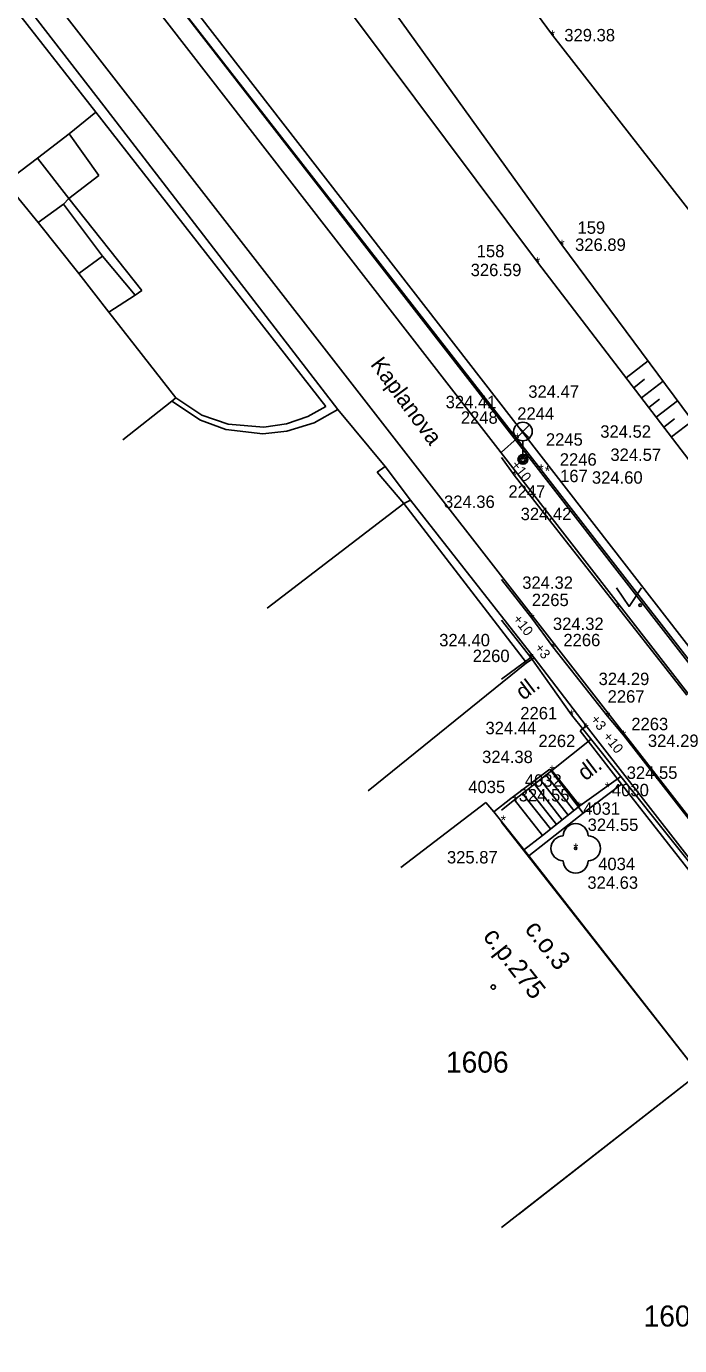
# Model space of a CAD drawing. Extents: x -600587 to -600377, y -1159886 to -1159708.
# Drawn here: x -600539.9 to -600513.6, y -1159856.5 to -1159803.3 of the extents above; entities that cross this region are included whole.
import ezdxf

# ---------------------------------------------------------------- set-up
doc = ezdxf.new("R2010")
doc.units = 0
for name, color, linetype in [('Hranice parcel', 7, 'Continuous'), ('Level 33', 7, 'Continuous'), ('Parcelní čísla', 7, 'Continuous'), ('Vnitřní kresba', 7, 'Continuous'), ('Vrstva 10', 7, 'Continuous'), ('Vrstva 11', 7, 'Continuous'), ('Vrstva 16', 7, 'Continuous'), ('Vrstva 20', 7, 'Continuous'), ('Vrstva 22', 7, 'Continuous'), ('Vrstva 36', 7, 'Continuous'), ('Vrstva 40', 7, 'Continuous'), ('Vrstva 46', 7, 'Continuous'), ('Vrstva 58', 7, 'Continuous'), ('Vrstva 59', 7, 'Continuous'), ('Vrstva 60', 7, 'Continuous'), ('Vrstva 7', 7, 'Continuous'), ('Značky budov', 7, 'Continuous')]:
    doc.layers.add(name, color=color, linetype=linetype)

msp = doc.modelspace()

# ---------------------------------------------------------------- linework, layer by layer
at = {"layer": 'Hranice parcel'}
msp.add_line((-600519.44, -1159828.81), (-600524.43, -1159822.45), dxfattribs=at)
for points in [[(-600488.61, -1159847.98), (-600490.62, -1159848.62), (-600491.99, -1159848.82), (-600493.39, -1159848.77), (-600494.93, -1159848.62), (-600496.36, -1159848.13), (-600500.23, -1159845.75), (-600572.32, -1159752.89), (-600572.98, -1159751.48), (-600573.33, -1159750.24), (-600573.44, -1159748.95), (-600573.44, -1159747.6), (-600573.32, -1159746.25), (-600573.13, -1159744.93), (-600572.66, -1159743.72), (-600571.05, -1159741.4), (-600570.22, -1159740.33), (-600564.67, -1159736.09)], [(-600524.43, -1159822.45), (-600525.46, -1159821.09), (-600527.36, -1159818.8), (-600536.8, -1159806.55), (-600551.99, -1159786.94)], [(-600530.213, -1159826.814), (-600524.7, -1159822.59), (-600524.43, -1159822.45)], [(-600519.44, -1159828.81), (-600519.76, -1159829.02), (-600526.14, -1159834.179)], [(-600508.85, -1159842.47), (-600517.35, -1159831.56), (-600519.44, -1159828.81)], [(-600520.064, -1159851.241), (-600512.8, -1159845.57), (-600512.33, -1159845.23), (-600509.08, -1159842.66), (-600508.85, -1159842.47)]]:
    msp.add_lwpolyline(points, dxfattribs=at)
at = {"layer": 'Level 33'}
for p, q in [((-600520.163, -1159819.947), (-600519.633, -1159819.417)), ((-600520.163, -1159819.417), (-600519.633, -1159819.947)), ((-600519.898, -1159820.057), (-600519.898, -1159820.807))]:
    msp.add_line(p, q, dxfattribs=at)
for centre, radius in [((-600519.898, -1159819.682), 0.375), ((-600519.898, -1159820.807), 0.2), ((-600519.898, -1159820.807), 0.145), ((-600519.898, -1159820.807), 0.0876)]:
    msp.add_circle(centre, radius, dxfattribs=at)
at = {"layer": 'Vnitřní kresba'}
for p, q in [((-600580.267, -1159748.971), (-600497.15, -1159855.9)), ((-600499.96, -1159845.44), (-600571.89, -1159752.7)), ((-600503.93, -1159842.26), (-600567.61, -1159760.2)), ((-600537.12, -1159806.8), (-600552.47, -1159787.22)), ((-600538.2, -1159807.68), (-600537.12, -1159806.8)), ((-600527.85, -1159818.67), (-600537.12, -1159806.8)), ((-600539.47, -1159808.66), (-600538.2, -1159807.68)), ((-600538.2, -1159807.68), (-600537, -1159809.36)), ((-600540.77, -1159809.64), (-600539.47, -1159808.66)), ((-600539.47, -1159808.66), (-600538.21, -1159810.29)), ((-600537, -1159809.36), (-600538.21, -1159810.29)), ((-600540.77, -1159809.64), (-600539.44, -1159811.25)), ((-600538.43, -1159810.52), (-600539.44, -1159811.25)), ((-600538.21, -1159810.29), (-600538.43, -1159810.52)), ((-600538.43, -1159810.52), (-600536.85, -1159812.62)), ((-600538.21, -1159810.29), (-600535.26, -1159814)), ((-600539.44, -1159811.25), (-600537.81, -1159813.31)), ((-600537.81, -1159813.31), (-600536.85, -1159812.62)), ((-600536.85, -1159812.62), (-600535.54, -1159814.19)), ((-600537.81, -1159813.31), (-600536.59, -1159814.87)), ((-600535.54, -1159814.19), (-600536.59, -1159814.87)), ((-600535.26, -1159814), (-600535.54, -1159814.19)), ((-600536.59, -1159814.87), (-600533.9, -1159818.33)), ((-600534.06, -1159818.46), (-600536.028, -1159820.024)), ((-600533.9, -1159818.33), (-600534.06, -1159818.46)), ((-600534.06, -1159818.46), (-600532.9, -1159819.23)), ((-600533.9, -1159818.33), (-600532.85, -1159819.03)), ((-600531.79, -1159819.39), (-600532.85, -1159819.03)), ((-600529.43, -1159819.37), (-600528.57, -1159819.08)), ((-600527.85, -1159818.67), (-600528.57, -1159819.08)), ((-600527.36, -1159818.8), (-600528.31, -1159819.34)), ((-600531.88, -1159819.6), (-600532.9, -1159819.23)), ((-600531.88, -1159819.6), (-600530.39, -1159819.78)), ((-600531.79, -1159819.39), (-600530.35, -1159819.51)), ((-600529.43, -1159819.37), (-600530.35, -1159819.51)), ((-600529.42, -1159819.67), (-600528.31, -1159819.34)), ((-600529.42, -1159819.67), (-600530.39, -1159819.78)), ((-600525.46, -1159821.09), (-600525.77, -1159821.33)), ((-600525.77, -1159821.33), (-600524.7, -1159822.59)), ((-600524.7, -1159822.59), (-600519.76, -1159829.02)), ((-600517.35, -1159831.56), (-600517.59, -1159831.76)), ((-600517.59, -1159831.76), (-600515.92, -1159833.9)), ((-600520.38, -1159834.48), (-600518.81, -1159833.3)), ((-600518.81, -1159833.3), (-600517.47, -1159835.08)), ((-600517.47, -1159835.08), (-600515.92, -1159833.9)), ((-600515.92, -1159833.9), (-600509.08, -1159842.66)), ((-600521.07, -1159835.02), (-600520.38, -1159834.48)), ((-600524.823, -1159837.271), (-600521.39, -1159834.65)), ((-600521.39, -1159834.65), (-600521.07, -1159835.02)), ((-600521.07, -1159835.02), (-600519.66, -1159836.79)), ((-600518.98, -1159836.26), (-600517.47, -1159835.08)), ((-600519.66, -1159836.79), (-600518.98, -1159836.26)), ((-600519.66, -1159836.79), (-600512.8, -1159845.57))]:
    msp.add_line(p, q, dxfattribs=at)
at = {"layer": 'Vrstva 10'}
for p, q in [((-600519.583, -1159828.799), (-600517.941, -1159831.105)), ((-600517.941, -1159831.105), (-600517.443, -1159831.729))]:
    msp.add_line(p, q, dxfattribs=at)
at = {"layer": 'Vrstva 11'}
for p, q in [((-600515.73, -1159817.52), (-600514.85, -1159816.84)), ((-600515.43, -1159817.92), (-600514.99, -1159817.58)), ((-600515.12, -1159818.32), (-600514.25, -1159817.65)), ((-600514.82, -1159818.71), (-600514.39, -1159818.38)), ((-600514.52, -1159819.11), (-600513.66, -1159818.45)), ((-600514.21, -1159819.51), (-600513.78, -1159819.18)), ((-600513.91, -1159819.9), (-600513.06, -1159819.25)), ((-600520.767, -1159820.512), (-600520.128, -1159819.959)), ((-600520.767, -1159820.735), (-600520.248, -1159821.439)), ((-600520.248, -1159821.439), (-600513.287, -1159830.311)), ((-600520.767, -1159825.65), (-600519.539, -1159827.217)), ((-600519.539, -1159827.217), (-600518.688, -1159828.374)), ((-600518.688, -1159828.374), (-600516.483, -1159831.169)), ((-600519.583, -1159828.799), (-600520.767, -1159829.678)), ((-600516.483, -1159831.169), (-600515.844, -1159831.929)), ((-600517.153, -1159832.092), (-600518.731, -1159833.352)), ((-600515.844, -1159831.929), (-600508.09, -1159841.905)), ((-600520.239, -1159834.538), (-600518.731, -1159833.352)), ((-600518.731, -1159833.352), (-600517.604, -1159834.785)), ((-600519.438, -1159833.908), (-600518.311, -1159835.341)), ((-600519.203, -1159833.723), (-600518.076, -1159835.156)), ((-600518.967, -1159833.537), (-600517.84, -1159834.97)), ((-600515.957, -1159833.591), (-600517.604, -1159834.785)), ((-600519.91, -1159834.279), (-600518.783, -1159835.712)), ((-600519.674, -1159834.094), (-600518.547, -1159835.527)), ((-600520.767, -1159834.954), (-600520.239, -1159834.538)), ((-600520.239, -1159834.538), (-600519.112, -1159835.971)), ((-600517.604, -1159834.785), (-600519.112, -1159835.971)), ((-600519.877, -1159836.573), (-600519.112, -1159835.971))]:
    msp.add_line(p, q, dxfattribs=at)
for points in [[(-600502.72, -1159834.41), (-600509.56, -1159825.58), (-600519.31, -1159812.85), (-600530.48, -1159797.91), (-600554.16, -1159766.46)], [(-600541.29, -1159772.5), (-600530.96, -1159787.09), (-600518.71, -1159803.7), (-600511.21, -1159813.31), (-600502.87, -1159824.07)], [(-600508.65, -1159825.2), (-600518.33, -1159812.15), (-600529.24, -1159796.96), (-600545.67, -1159772.91)]]:
    msp.add_lwpolyline(points, dxfattribs=at)
at = {"layer": 'Vrstva 20'}
for points in [[(-600512.8, -1159845.57), (-600520.767, -1159835.442)], [(-600502.538, -1159860.037), (-600504.48, -1159857.53), (-600503.89, -1159857.08), (-600512.8, -1159845.57), (-600520.767, -1159851.79)]]:
    msp.add_lwpolyline(points, dxfattribs=at)
at = {"layer": 'Vrstva 22'}
msp.add_circle((-600517.771, -1159836.495), 0.05, dxfattribs=at)
for centre, start, end in [((-600517.771, -1159835.995), 0, 180), ((-600518.271, -1159836.495), 90, 270), ((-600517.271, -1159836.495), 270, 90), ((-600517.771, -1159836.995), 180, 0)]:
    msp.add_arc(centre, 0.5, start, end, dxfattribs=at)
at = {"layer": 'Vrstva 36'}
msp.add_lwpolyline([(-600516.121, -1159825.991), (-600515.621, -1159826.741), (-600515.121, -1159825.991)], dxfattribs=at)
for centre in [(-600516.071, -1159826.69), (-600515.171, -1159826.69)]:
    msp.add_circle(centre, 0.05, dxfattribs=at)
at = {"layer": 'Vrstva 7'}
for p, q in [((-600520.767, -1159827.291), (-600519.583, -1159828.799)), ((-600508.91, -1159842.42), (-600517.443, -1159831.729))]:
    msp.add_line(p, q, dxfattribs=at)
msp.add_lwpolyline([(-600566.21, -1159760.89), (-600549.54, -1159782.24), (-600535.27, -1159800.58), (-600519.17, -1159821.21), (-600501, -1159844.58)], dxfattribs=at)
at = {"layer": 'Značky budov'}
msp.add_circle((-600521.093, -1159842.09), 0.0875, dxfattribs=at)

# ---------------------------------------------------------------- texts
at = {"layer": 'Parcelní čísla'}
for s, p in [('1606', (-600523.003, -1159845.54)), ('1608', (-600515.033, -1159855.78))]:
    msp.add_text(s, height=0.85, dxfattribs=at).set_placement(p)
at = {"layer": 'Vrstva 16'}
for s, p in [('+10', (-600520.404, -1159821.045)), ('+10', (-600520.328, -1159827.257)), ('+3', (-600519.449, -1159828.419)), ('+3', (-600517.197, -1159831.303)), ('+10', (-600516.695, -1159831.995))]:
    msp.add_text(s, height=0.4, rotation=308.3679, dxfattribs=at).set_placement(p)
at = {"layer": 'Vrstva 40'}
for s, rotation, p in [('Kaplanova', 306.4091, (-600526.074, -1159816.985)), ('dl.', 37.3346, (-600519.882, -1159830.547)), ('dl.', 37.3346, (-600517.383, -1159833.798))]:
    msp.add_text(s, height=0.65, rotation=rotation, dxfattribs=at).set_placement(p)
at = {"layer": 'Vrstva 46'}
for s, p in [('c.p.275', (-600521.542, -1159840.061)), ('c.o.3', (-600519.858, -1159839.763))]:
    msp.add_text(s, height=0.75, rotation=308.2142, dxfattribs=at).set_placement(p)
at = {"layer": 'Vrstva 58'}
for s, p in [('329.38', (-600518.229, -1159803.95)), ('326.89', (-600517.795, -1159812.4)), ('326.59', (-600522.006, -1159813.419)), ('324.47', (-600519.682, -1159818.324)), ('324.41', (-600523.014, -1159818.745)), ('324.52', (-600516.779, -1159819.935)), ('324.57', (-600516.371, -1159820.87)), ('324.60', (-600517.116, -1159821.789)), ('324.36', (-600523.08, -1159822.767)), ('324.42', (-600519.99, -1159823.259)), ('324.32', (-600519.926, -1159826.028)), ('324.32', (-600518.688, -1159827.689)), ('324.40', (-600523.274, -1159828.347)), ('324.29', (-600516.847, -1159829.91)), ('324.44', (-600521.408, -1159831.891)), ('324.29', (-600514.859, -1159832.405)), ('324.38', (-600521.544, -1159833.055)), ('324.55', (-600515.713, -1159833.693)), ('324.55', (-600520.068, -1159834.602)), ('324.55', (-600517.289, -1159835.793)), ('325.87', (-600522.962, -1159837.104)), ('324.63', (-600517.3, -1159838.125))]:
    msp.add_text(s, height=0.5, dxfattribs=at).set_placement(p)
at = {"layer": 'Vrstva 59'}
for s, p in [('159', (-600517.696, -1159811.712)), ('158', (-600521.761, -1159812.657)), ('2248', (-600522.402, -1159819.37)), ('2244', (-600520.128, -1159819.209)), ('2245', (-600518.972, -1159820.256)), ('2246', (-600518.412, -1159821.062)), ('167', (-600518.399, -1159821.727)), ('2247', (-600520.483, -1159822.354)), ('2265', (-600519.539, -1159826.725)), ('2266', (-600518.266, -1159828.345)), ('2260', (-600521.924, -1159828.982)), ('2267', (-600516.483, -1159830.618)), ('2261', (-600520.005, -1159831.293)), ('2263', (-600515.527, -1159831.73)), ('2262', (-600519.274, -1159832.41)), ('4035', (-600522.101, -1159834.266)), ('4032', (-600519.821, -1159834.009)), ('4030', (-600516.307, -1159834.394)), ('4031', (-600517.471, -1159835.14)), ('4034', (-600516.863, -1159837.372))]:
    msp.add_text(s, height=0.5, dxfattribs=at).set_placement(p)
at = {"layer": 'Vrstva 60'}
for p in [(-600518.808, -1159803.9), (-600518.428, -1159812.35), (-600519.408, -1159813.05), (-600520.226, -1159820.159), (-600519.996, -1159821.007), (-600519.268, -1159821.41), (-600519.014, -1159821.473), (-600520.346, -1159821.639), (-600519.637, -1159827.417), (-600519.681, -1159828.999), (-600518.786, -1159828.574), (-600518.039, -1159831.305), (-600516.581, -1159831.369), (-600517.45, -1159831.857), (-600515.942, -1159832.129), (-600518.829, -1159833.552), (-600516.603, -1159834.229), (-600520.317, -1159834.763), (-600517.742, -1159835.016), (-600520.792, -1159835.563), (-600517.869, -1159836.695)]:
    msp.add_text('*', height=0.4, dxfattribs=at).set_placement(p)

doc.saveas('drawing.dxf')
